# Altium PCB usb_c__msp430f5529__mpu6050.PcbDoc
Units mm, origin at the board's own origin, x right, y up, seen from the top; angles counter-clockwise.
Board outline 82 x 52 mm, 2 copper layers (Top, Bottom), stack 0 mm thick; 32 components, 26 nets, 203 pads, 80 vias.
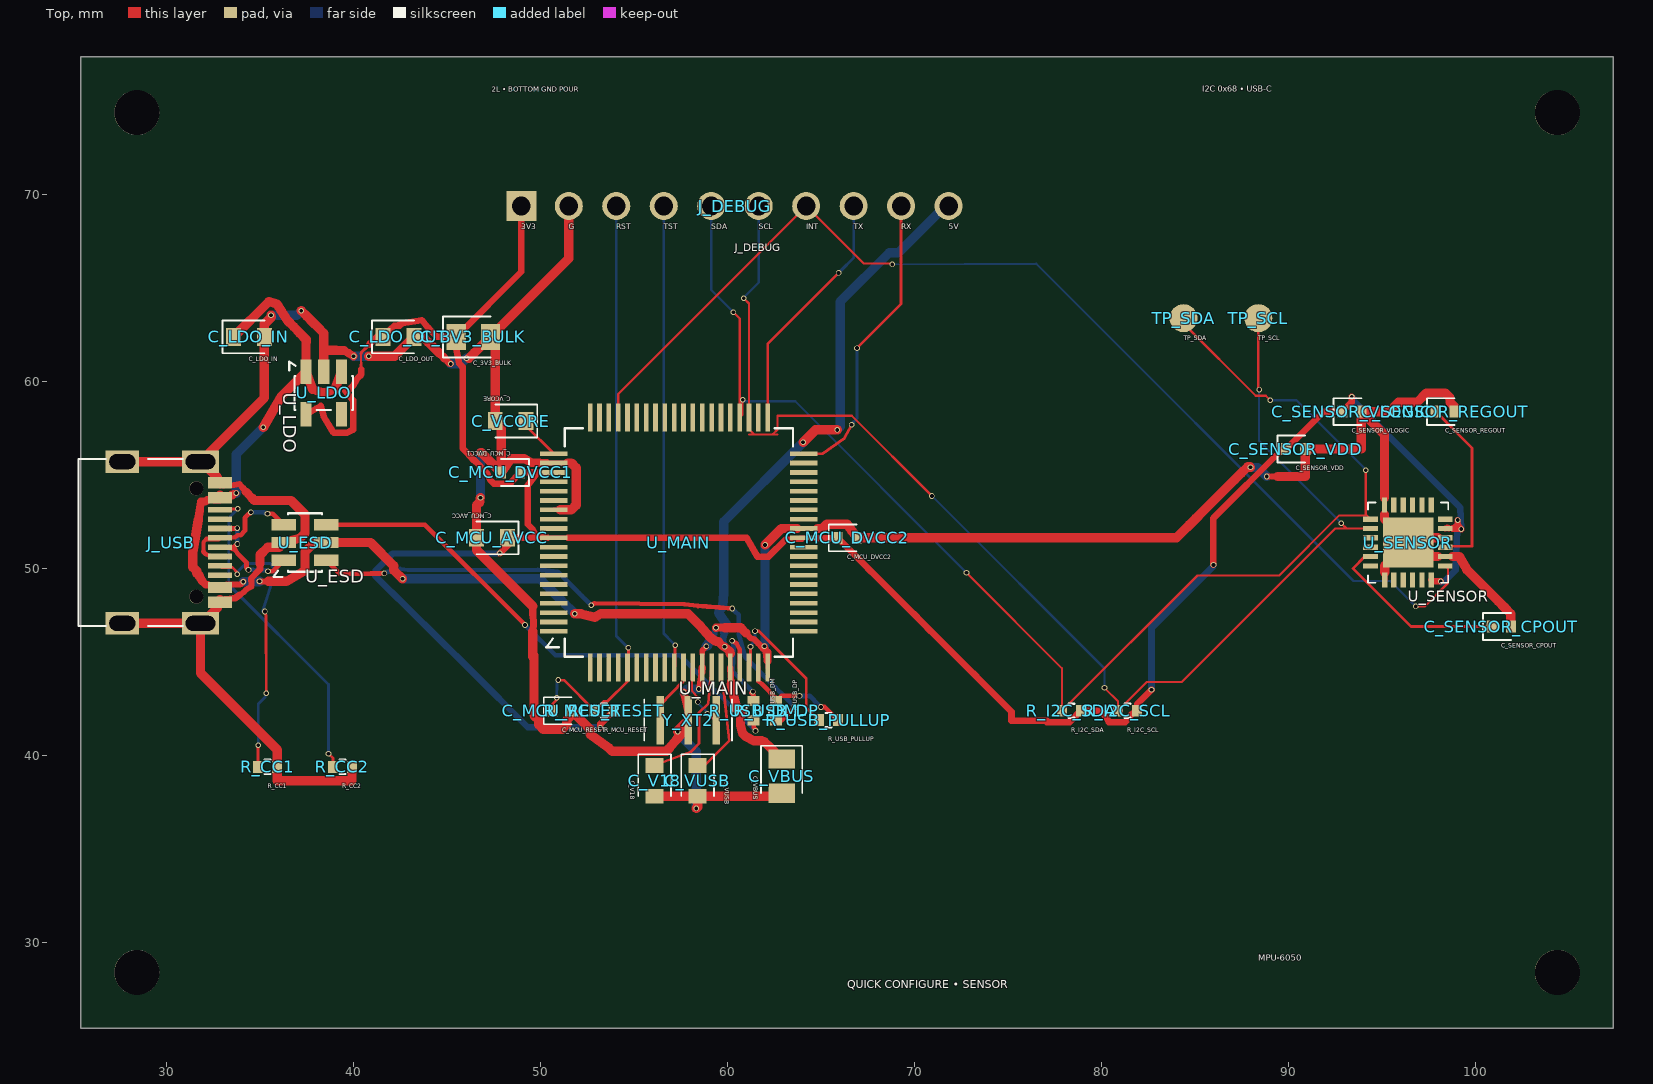
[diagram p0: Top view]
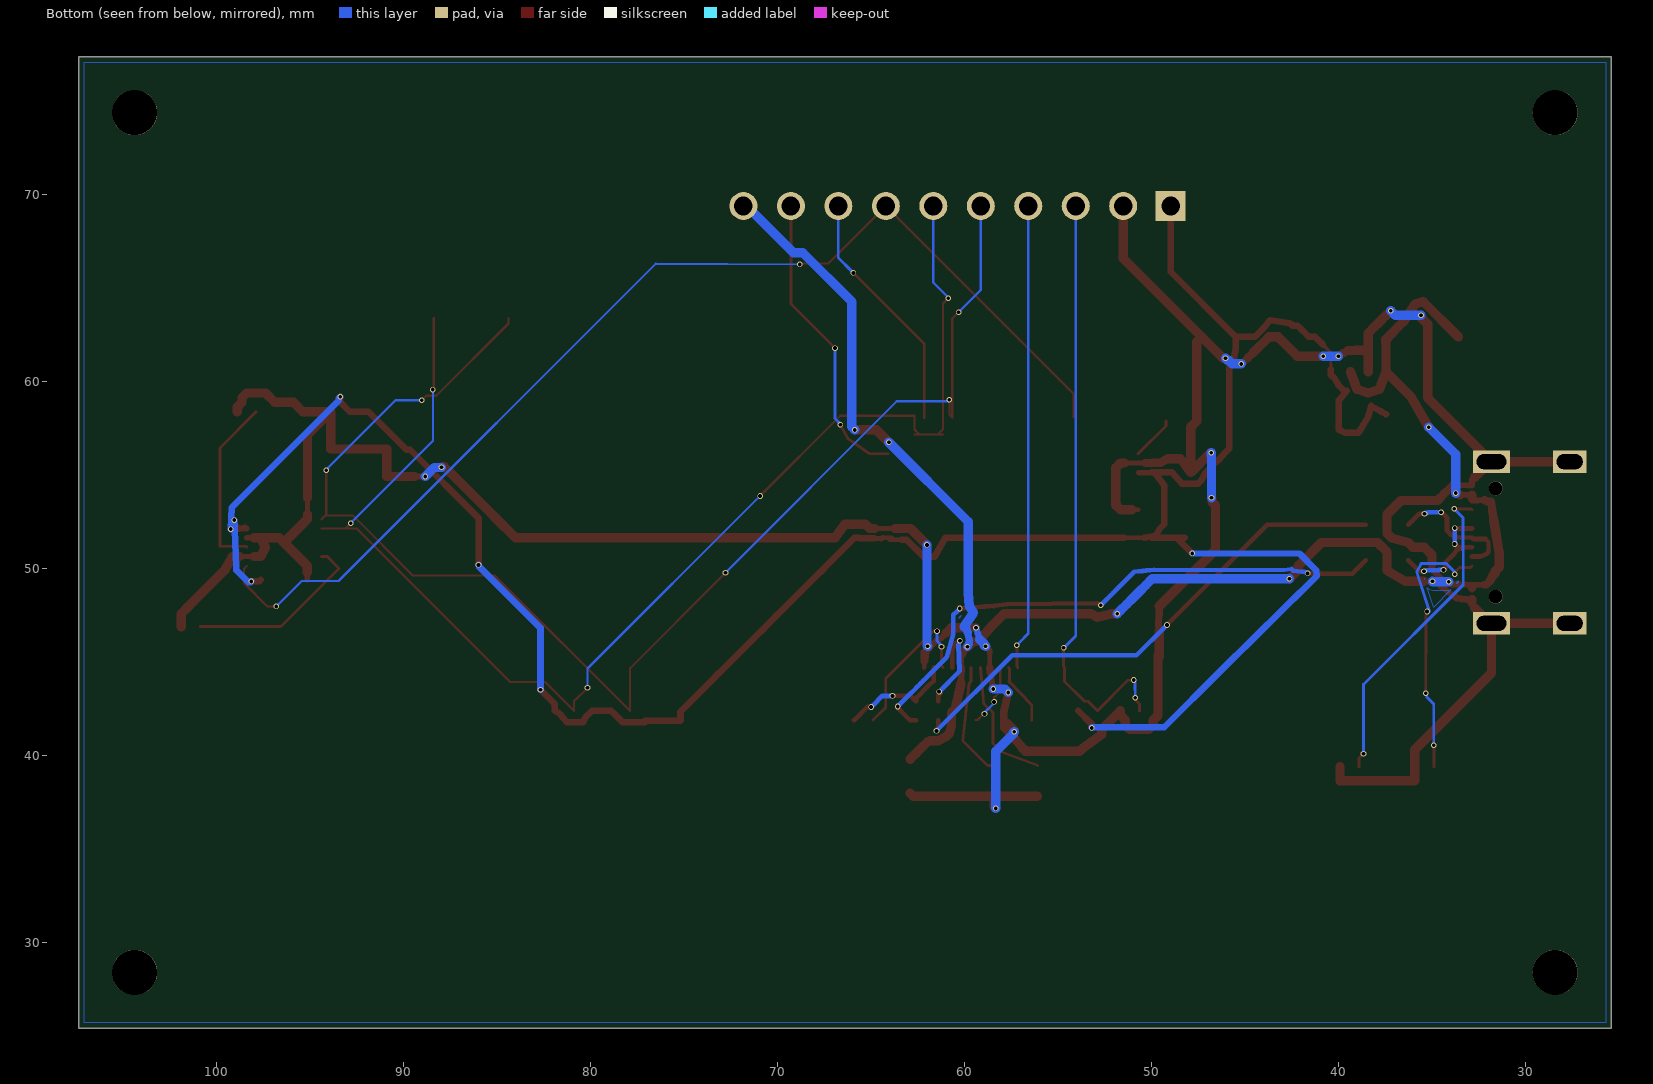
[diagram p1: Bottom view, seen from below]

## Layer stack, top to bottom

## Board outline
25.4,77.4 107.4,77.4 107.4,25.4 25.4,25.4

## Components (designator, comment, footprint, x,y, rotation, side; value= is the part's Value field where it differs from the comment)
C_3V3_BULK "" TSCIRCUIT-2.8500x1.4000mm 46.4,62.4 r0 top
C_LDO_IN "" TSCIRCUIT-2.4500x0.9500mm 34.4,62.4 r0 top
C_LDO_OUT "" TSCIRCUIT-2.4500x0.9500mm 42.4,62.4 r0 top
C_MCU_AVCC "" TSCIRCUIT-2.4500x0.9500mm 47.4,51.65 r180 top
C_MCU_DVCC1 "" TSCIRCUIT-1.5600x0.6400mm 48.4,55.15 r180 top
C_MCU_DVCC2 "" TSCIRCUIT-1.5600x0.6400mm 66.4,51.65 r0 top
C_MCU_RESET "" TSCIRCUIT-1.5600x0.6400mm 51.15,42.4 r0 top
C_SENSOR_CPOUT "" TSCIRCUIT-1.5600x0.6400mm 101.4,46.9 r0 top
C_SENSOR_REGOUT "" TSCIRCUIT-1.5600x0.6400mm 98.4,58.4 r0 top
C_SENSOR_VDD "" TSCIRCUIT-1.5600x0.6400mm 90.4,56.4 r0 top
C_SENSOR_VLOGIC "" TSCIRCUIT-1.5600x0.6400mm 93.4,58.4 r0 top
C_V18 "" TSCIRCUIT-0.9500x2.4500mm 56.1,38.65 r270 top
C_VBUS "" TSCIRCUIT-1.4000x2.8500mm 62.9,38.9 r270 top
C_VCORE "" TSCIRCUIT-2.4500x0.9500mm 48.4,57.9 r180 top
C_VUSB "" TSCIRCUIT-0.9500x2.4500mm 58.4,38.65 r270 top
J_DEBUG "" TSCIRCUIT-24.3600x1.5000mm 60.4,69.4 r0 top
J_USB "" TSCIRCUIT-6.7732x9.8502mm 30.113,51.4 r90 top
R_CC1 "" TSCIRCUIT-1.5600x0.6400mm 35.4,39.4 r0 top
R_CC2 "" TSCIRCUIT-1.5600x0.6400mm 39.4,39.4 r0 top
R_I2C_SCL "" TSCIRCUIT-1.5600x0.6400mm 81.4,42.4 r0 top
R_I2C_SDA "" TSCIRCUIT-1.5600x0.6400mm 78.4,42.4 r0 top
R_MCU_RESET "" TSCIRCUIT-1.5600x0.6400mm 53.4,42.4 r0 top
R_USB_DM "" TSCIRCUIT-0.6400x1.5600mm 61.4,42.4 r90 top
R_USB_DP "" TSCIRCUIT-0.6400x1.5600mm 62.6,42.4 r90 top
R_USB_PULLUP "" TSCIRCUIT-1.5600x0.6400mm 65.4,41.9 r0 top
TP_SCL "" TSCIRCUIT-1.5000x1.5000mm 88.4,63.4 r0 top
TP_SDA "" TSCIRCUIT-1.5000x1.5000mm 84.4,63.4 r0 top
U_ESD "" TSCIRCUIT-3.6000x2.5000mm 37.4,51.4 r0 top
U_LDO "" TSCIRCUIT-2.5000x3.6000mm 38.4,59.4 r270 top
U_MAIN "" TSCIRCUIT-14.8500x14.8500mm 57.4,51.4 r0 top
U_SENSOR "" TSCIRCUIT-4.8000x4.8000mm 96.4,51.4 r0 top
Y_XT2 "" TSCIRCUIT-3.4000x2.6000mm 57.9,41.9 r270 top

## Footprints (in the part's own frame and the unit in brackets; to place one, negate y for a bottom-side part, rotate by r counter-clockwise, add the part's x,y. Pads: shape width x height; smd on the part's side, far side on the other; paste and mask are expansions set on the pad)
TSCIRCUIT-0.6400x1.5600mm [mm]
  rect 0.54x0.64 smd: 1(-0.51,0) 2(0.51,0)
  silkscreen extent -0.15,-0.38 0.15,0.38
TSCIRCUIT-0.9500x2.4500mm [mm]
  rect 0.8x0.95 smd: 1(-0.825,0) 2(0.825,0)
  silkscreen extent -1.43,-0.87 0.82,0.87
TSCIRCUIT-1.4000x2.8500mm [mm]
  rect 1.025x1.4 smd: 1(-0.913,0) 2(0.913,0)
  silkscreen extent -1.62,-1.1 0.91,1.1
TSCIRCUIT-1.5000x1.5000mm [mm]
  round 1.5 smd: 1(0,0)
TSCIRCUIT-1.5600x0.6400mm [mm]
  rect 0.54x0.64 smd: 1(-0.51,0) 2(0.51,0)
  silkscreen extent -0.98,-0.72 0.51,0.72
TSCIRCUIT-2.4500x0.9500mm [mm]
  rect 0.8x0.95 smd: 1(-0.825,0) 2(0.825,0)
  silkscreen extent -1.43,-0.87 0.82,0.87
TSCIRCUIT-2.5000x3.6000mm [mm]
  rect 1.325x0.6 smd: 1(-1.137,-0.95) 2(-1.137,0) 3(-1.137,0.95) 4(1.138,0.95) 5(1.138,-0.95)
  silkscreen extent -1.69,-1.84 0.91,1.56
TSCIRCUIT-2.8500x1.4000mm [mm]
  rect 1.025x1.4 smd: 1(-0.913,0) 2(0.913,0)
  silkscreen extent -1.63,-1.1 0.91,1.1
TSCIRCUIT-3.4000x2.6000mm [mm]
  rect 2.6x0.4 smd: 1(0,1.5) 2(0,0) 3(0,-1.5)
  silkscreen extent -1.1,-2.35 1.1,2.35
TSCIRCUIT-3.6000x2.5000mm [mm]
  rect 1.325x0.6 smd: 1(-1.137,-0.95) 2(-1.137,0) 3(-1.137,0.95) 4(1.138,0.95) 5(1.138,0) 6(1.138,-0.95)
  silkscreen extent -1.69,-1.84 0.91,1.56
TSCIRCUIT-4.8000x4.8000mm [mm]
  rect 0.28x0.8 smd: 1(-1.25,2) 2(-0.75,2) 3(-0.25,2) 4(0.25,2) 5(0.75,2) 6(1.25,2) 13(1.25,-2) 14(0.75,-2) 15(0.25,-2) 16(-0.25,-2) 17(-0.75,-2) 18(-1.242,-2)
  rect 0.8x0.28 smd: 7(2,1.25) 8(2,0.75) 9(2,0.25) 10(2,-0.25) 11(2,-0.75) 12(2,-1.25) 19(-2,-1.25) 20(-2,-0.75) 21(-2,-0.25) 22(-2,0.25) 23(-2,0.75) 24(-2,1.25)
  rect 2.7x2.7 smd: 25(0.012,0)
  silkscreen extent -2.14,-2.15 2.16,2.15
TSCIRCUIT-6.7732x9.8502mm [mm]
  rect 0.3x1.3 smd: 1(-3.35,-2.737) 2(-3.05,-2.737) 3(-2.55,-2.737) 4(-2.25,-2.737) 5(-1.75,-2.737) 6(-1.25,-2.737) 7(-0.75,-2.737) 8(-0.25,-2.737) 9(0.25,-2.737) 10(0.75,-2.737) 11(1.25,-2.737) 12(1.75,-2.737) 13(2.55,-2.737) 14(2.25,-2.737) 15(3.35,-2.737) 16(3.05,-2.737)
  rect 1.2x2 hole 0.8 slot 1.6 at 90 deg: 17(-4.325,-1.693) 18(4.325,-1.693)
  rect 1.2x1.8 hole 0.8 slot 1.4 at 90 deg: 19(4.325,2.487) 20(-4.325,2.487)
  round 0.75 hole 0.75 unplated: NPTH-1(-2.9,-1.468) NPTH-2(2.9,-1.468)
  silkscreen extent -4.47,-0.75 4.47,4.83
TSCIRCUIT-14.8500x14.8500mm [mm]
  rect 1.475x0.25 smd: 1(-6.687,-4.75) 2(-6.687,-4.25) 3(-6.687,-3.75) 4(-6.687,-3.25) 5(-6.687,-2.75) 6(-6.687,-2.25) 7(-6.687,-1.75) 8(-6.687,-1.25) 9(-6.687,-0.75) 10(-6.687,-0.25) 11(-6.687,0.25) 12(-6.687,0.75) 13(-6.687,1.25) 14(-6.687,1.75) 15(-6.687,2.25) 16(-6.687,2.75) 17(-6.687,3.25) 18(-6.687,3.75) 19(-6.687,4.25) 20(-6.687,4.75) 41(6.687,4.75) 42(6.687,4.25) 43(6.687,3.75) 44(6.687,3.25) 45(6.687,2.75) 46(6.687,2.25) 47(6.687,1.75) 48(6.687,1.25) 49(6.687,0.75) 50(6.687,0.25) 51(6.687,-0.25) 52(6.687,-0.75) 53(6.687,-1.25) 54(6.687,-1.75) 55(6.687,-2.25) 56(6.687,-2.75) 57(6.687,-3.25) 58(6.687,-3.75) 59(6.687,-4.25) 60(6.687,-4.75)
  rect 0.25x1.475 smd: 21(-4.75,6.687) 22(-4.25,6.687) 23(-3.75,6.687) 24(-3.25,6.687) 25(-2.75,6.687) 26(-2.25,6.687) 27(-1.75,6.687) 28(-1.25,6.687) 29(-0.75,6.687) 30(-0.25,6.687) 31(0.25,6.687) 32(0.75,6.687) 33(1.25,6.687) 34(1.75,6.687) 35(2.25,6.687) 36(2.75,6.687) 37(3.25,6.687) 38(3.75,6.687) 39(4.25,6.687) 40(4.75,6.687) 61(4.75,-6.687) 62(4.25,-6.687) 63(3.75,-6.687) 64(3.25,-6.687) 65(2.75,-6.687) 66(2.25,-6.687) 67(1.75,-6.687) 68(1.25,-6.687) 69(0.75,-6.687) 70(0.25,-6.687) 71(-0.25,-6.687) 72(-0.75,-6.687) 73(-1.25,-6.687) 74(-1.75,-6.687) 75(-2.25,-6.687) 76(-2.75,-6.687) 77(-3.25,-6.687) 78(-3.75,-6.687) 79(-4.25,-6.687) 80(-4.75,-6.687)
  silkscreen extent -7.09,-6.11 6.11,6.11
TSCIRCUIT-24.3600x1.5000mm [mm]
  rect 1.6x1.6 hole 1: 1(-11.43,0)
  round 1.5 hole 1: 2(-8.89,0) 3(-6.35,0) 4(-3.81,0) 5(-1.27,0) 6(1.27,0) 7(3.81,0) 8(6.35,0) 9(8.89,0) 10(11.43,0)

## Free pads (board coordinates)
  round 2.4 hole 2.4 unplated: NPTH-3(28.4,28.4) NPTH-4(104.4,28.4) NPTH-5(28.4,74.4) NPTH-6(104.4,74.4)

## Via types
v1: diameter 0.3, hole 0.2, Top to Bottom, 80 vias

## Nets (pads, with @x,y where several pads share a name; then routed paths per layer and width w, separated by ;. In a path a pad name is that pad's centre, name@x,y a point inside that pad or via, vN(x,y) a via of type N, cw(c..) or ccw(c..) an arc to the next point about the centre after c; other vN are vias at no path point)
".J_DEBUG > .pin4 to .U_MAIN > .pin71": J_DEBUG.4 U_MAIN.71 | length 25
  Top w0.15: U_MAIN.71 57.2,44.762 v1(57.2,45.906)
  Bottom w0.15: J_DEBUG.4 56.59,46.53 57.036,46.085 57.036,46.07 v1(57.2,45.906)
".J_DEBUG > .pin8 to .U_MAIN > .pin40": J_DEBUG.8 U_MAIN.40 | length 13.2
  Top w0.15: U_MAIN.40 62.15,62.028 v1(65.944,65.822)
  Bottom w0.15: v1(65.944,65.822) 66.057,65.935 66.057,65.937 66.75,66.63 J_DEBUG.8
".J_DEBUG > .pin9 to .U_MAIN > .pin41": J_DEBUG.9 U_MAIN.41 | length 16
  Top w0.15: U_MAIN.41 65.085,56.148 66.253,56.984 v1(66.641,57.7) ; v1(66.928,61.802) 67.007,61.881 69.29,64.164 J_DEBUG.9
  Bottom w0.15: v1(66.641,57.7) 66.647,57.714 66.647,57.753 66.928,58.034 v1(66.928,61.802)
GND: C_3V3_BULK.2 C_LDO_IN.2 C_LDO_OUT.2 C_MCU_AVCC.2 C_MCU_DVCC1.2 C_MCU_DVCC2.2 C_MCU_RESET.2 C_SENSOR_CPOUT.2 C_SENSOR_REGOUT.2 C_SENSOR_VDD.2 C_SENSOR_VLOGIC.2 C_V18.2 C_VBUS.2 C_VCORE.2 C_VUSB.2 J_DEBUG.2 J_USB.1 J_USB.2 J_USB.15 J_USB.16 J_USB.17 J_USB.18 J_USB.19 J_USB.20 R_CC1.2 R_CC2.2 U_ESD.2 U_LDO.2 U_MAIN.14 U_MAIN.19 U_MAIN.49 U_MAIN.61 U_MAIN.68 U_SENSOR.1 U_SENSOR.9 U_SENSOR.11 U_SENSOR.18 U_SENSOR.25 Y_XT2.2 | length 213.3
  Top w0.25: U_MAIN.14 U_MAIN.14@51.046,53.15 ; U_MAIN.19 U_MAIN.19@51.45,55.65 ; U_MAIN.68 58.65,45.166 U_MAIN.68@58.65,45.45 ; U_MAIN.61@62.119,45.056 U_MAIN.61 U_MAIN.61@62.15,45.052 ; U_MAIN.49@63.716,52.15 U_MAIN.49 64.552,52.15 U_MAIN.49@64.825,52.15
  Top w0.27: U_MAIN.19@50.327,55.655 U_MAIN.19
  Top w0.28: 95.15,52.9 95.15,53 95.15,53.025 95.15,53.15 95.15,53.275 U_SENSOR.1 95.15,53.525 95.15,53.65 95.15,53.775 95.15,53.8 ; U_SENSOR.18 95.158,49.525 95.158,49.65 95.158,49.775 95.158,49.8 ; U_SENSOR.11@98,50.65 U_SENSOR.11 98.8,50.65 ; U_SENSOR.9@98,51.65 U_SENSOR.9 98.025,51.65 U_SENSOR.9@98,51.65
  Top w0.3: J_USB.1@32.699,47.9 J_USB.1 J_USB.2@32.849,48.2 ; 32.699,54.9 J_USB.15 J_USB.16@32.849,54.6 ; J_USB.2 32.945,48.339 33.037,48.35 J_USB.2@33.13,48.35 ; J_USB.16 J_USB.16@32.945,54.461 ; 58.65,45.45 58.65,45.62 v1(58.873,45.843)
  Top w0.31: J_USB.16 J_USB.15@32.849,54.6 ; v1(46.035,61.257) v1@46.17,61.257
  Top w0.312: J_USB.16@32.945,54.461 33.037,54.45 33.314,54.465 33.592,54.479 33.9,54.525 ; 33.9,48.587 34.134,48.744 34.254,48.877 34.525,49.056
  Top w0.325: 34.525,49.056 34.521,49.482 34.758,49.727 ; v1(58.466,43.56) 58.527,43.886 58.588,44.212 U_MAIN.68@58.619,44.462 ; 60.99,46.552 61.28,46.262 61.4,46.244 61.634,46.009 v1@61.869,45.775 ; v1(88.853,54.932) 89.148,54.932 89.443,54.933
  Top w0.331: 33.9,54.525 34.068,54.322
  Top w0.35: 34.068,54.322 34.235,54.12 ; 34.758,49.727 34.994,49.971 ; v1@45.136,60.978 45.176,60.978 v1(45.198,60.956)
  Top w0.375: J_USB.2@33.13,48.35 33.398,48.391 33.666,48.431 33.9,48.587 ; 34.99,50.279 34.994,49.971 ; 44.851,61.262 v1@45.136,60.978 ; 49.589,46.639 49.619,47.088 49.589,47.535 ; v1@61.869,45.775 62.15,45.525 ; v1(61.976,45.843) U_MAIN.61@62.088,45.4
  Top w0.383: U_MAIN.61@62.088,45.4 U_MAIN.61@62.119,45.056
  Top w0.4: 49.589,47.535 49.59,47.983 ; 57.585,41.171 57.9,41.486 Y_XT2.2 ; v1(57.659,43.378) 57.9,42.346 Y_XT2.2 ; Y_XT2.2@57.7,41.7 Y_XT2.2 ; U_MAIN.68@58.619,44.462 U_MAIN.68 ; U_MAIN.61@62.15,45.052 62.15,45.525
  Top w0.425: v1(59.384,46.838) 59.388,46.842 59.451,46.842 59.867,46.842
  Top w0.437: 39.494,61.681 39.745,61.524 v1(39.996,61.367)
  Top w0.45: 34.235,54.12 34.58,53.765 ; 44.567,61.547 44.851,61.262 ; 49.556,55.666 49.942,55.66 U_MAIN.19@50.327,55.655
  Top w0.475: v1(35.576,63.564) v1@35.602,63.464 ; 39.056,61.681 39.494,61.681 ; 49.119,55.884 49.556,55.666 ; 60.701,46.842 60.99,46.552 ; v1@87.946,55.458 v1(87.983,55.421)
  Top w0.5: J_USB.20 J_USB.17 ; J_USB.19 J_USB.18 ; J_USB.1@32.699,47.9 32.474,47.675 31.874,47.075 J_USB.17 ; 32.699,54.9 32.474,55.125 31.874,55.725 J_USB.18 ; J_USB.1@32.849,48.2 J_USB.2 ; 34.58,53.765 34.695,53.65 35.65,53.65 36.65,53.65 37.4,52.9 37.4,51.9 37.15,51.65 U_ESD.2 36.013,51.15 35.4,51.15 34.987,50.737 34.987,50.586 34.99,50.279 ; v1@35.602,63.464 35.414,63.275 35.225,63.086 35.225,62.743 C_LDO_IN.2 35.225,59.144 J_USB.18 ; v1(37.2,63.8) 37.5,63.5 37.8,63.2 38.1,62.9 38.4,62.6 38.4,62.188 38.4,61.775 38.4,61.363 38.4,60.95 U_LDO.2 38.4,61.681 39.056,61.681 ; R_CC2.2 39.91,38.65 35.91,38.65 R_CC1.2 35.908,39.86 35.906,40.32 31.806,44.42 J_USB.17 ; v1(40.804,61.361) 40.809,61.366 40.903,61.366 41.333,61.366 41.762,61.366 42.191,61.366 42.536,61.711 42.88,62.055 C_LDO_OUT.2 43.713,62.4 43.998,62.116 44.282,61.831 44.567,61.547 ; v1@46.17,61.257 46.456,61.543 C_3V3_BULK.2 ; v1(46.787,53.8) 46.759,53.772 46.759,53.574 46.575,53.389 C_MCU_AVCC.2 46.575,50.998 49.59,47.983 ; v1(46.8,56.2) 46.84,56.2 C_MCU_DVCC1.2 ; 49.119,55.884 48.791,55.884 48.462,55.884 48.176,55.598 48.176,55.517 C_MCU_DVCC1.2 ; 49.589,46.639 49.589,46.191 49.589,45.743 49.588,45.295 49.65,45.357 49.65,42.15 49.9,41.9 49.9,41.65 50.15,41.4 51.15,41.4 51.4,41.65 51.4,41.9 51.66,42.16 C_MCU_RESET.2 52.65,41.41 52.65,41.15 53.639,40.421 53.827,40.233 56.733,40.233 56.9,40.4 57.27,40.856 57.585,41.171 ; U_MAIN.14@51.046,53.15 51.65,53.15 51.9,53.4 51.9,55.4 51.65,55.65 51.45,55.65 ; J_DEBUG.2 51.51,66.597 C_3V3_BULK.2 ; C_V18.2 C_VUSB.2 ; v1(57.342,41.276) 57.342,41.342 57.7,41.7 ; v1(58.327,37.175) 58.4,37.248 C_VUSB.2 ; 59.867,46.842 60.284,46.842 60.701,46.842 ; v1(62.011,51.27) 62.891,52.15 63.344,52.15 U_MAIN.49@63.716,52.15 ; C_VBUS.2 62.737,37.825 C_VUSB.2 ; 64.825,52.15 65.016,52.15 65.072,52.15 65.306,52.384 65.671,52.384 66.035,52.384 66.4,52.384 66.655,52.017 C_MCU_DVCC2.2 67.399,51.65 67.888,51.65 68.377,51.65 68.865,51.65 69.354,51.65 69.843,51.65 70.332,51.65 70.821,51.65 71.31,51.65 71.799,51.65 72.287,51.65 72.776,51.65 73.265,51.65 73.754,51.65 74.243,51.65 74.732,51.65 75.221,51.65 75.709,51.65 76.198,51.65 76.687,51.65 77.176,51.65 77.665,51.65 78.154,51.65 78.643,51.65 79.131,51.65 79.62,51.65 80.109,51.65 80.598,51.65 81.087,51.65 81.576,51.65 82.065,51.65 82.553,51.65 83.042,51.65 83.531,51.65 84.02,51.65 84.366,51.996 84.712,52.342 85.059,52.689 85.405,53.035 85.751,53.381 86.097,53.727 86.443,54.073 86.79,54.42 87.136,54.766 87.482,55.112 87.828,55.458 v1@87.946,55.458 ; 89.443,54.933 90.91,54.933 C_SENSOR_VDD.2 93.91,56.4 C_SENSOR_VLOGIC.2 ; 95.15,52.9 95.15,52.775 95.15,52.662 95.159,52.654 95.247,52.565 95.336,52.477 U_SENSOR.25 ; 95.15,53.8 95.15,53.9 95.15,54.025 95.15,54.15 95.15,54.275 95.15,54.4 95.15,57.16 C_SENSOR_VLOGIC.2 ; 95.158,49.8 95.158,49.9 95.158,50.025 95.158,50.145 95.161,50.149 95.25,50.237 95.338,50.325 U_SENSOR.25 ; U_SENSOR.11@98,50.65 97.762,50.65 97.65,50.65 97.4,51.15 U_SENSOR.25@97.65,51.65 ; 98.8,50.65 99.15,50.65 99.558,49.946 99.894,49.61 100.23,49.274 100.566,48.938 100.902,48.602 101.238,48.266 101.574,47.93 101.91,47.594 101.91,47.247 C_SENSOR_CPOUT.2 ; C_SENSOR_REGOUT.2 98.9,58.4 98.9,58.65 98.65,58.9 98.65,59.15 98.4,59.4 97.4,59.4 96.9,58.9 95.9,58.9 95.4,58.4 C_SENSOR_VLOGIC.2 ; C_3V3_BULK.2 47.575,62.138 C_VCORE.2 47.89,57.585 C_MCU_DVCC1.2 ; U_SENSOR.25 96.662,51.65 97.4,51.65 97.525,51.65 U_SENSOR.25@97.65,51.65 ; U_SENSOR.25@97.65,51.65 97.762,51.65 98,51.65 97.9,51.65 97.775,51.65 U_SENSOR.25@97.65,51.65
  Bottom w0.35: 59.182,46.209 59.283,46.523 v1(59.384,46.838)
  Bottom w0.475: v1(87.983,55.421) 88.36,55.421 88.579,55.202
  Bottom w0.5: v1(35.576,63.564) 36.964,63.564 v1(37.2,63.8) ; v1(39.996,61.367) 39.999,61.364 40.057,61.364 40.06,61.361 40.432,61.361 v1(40.804,61.361) ; v1(45.198,60.956) 45.673,60.956 45.867,61.15 45.928,61.15 v1(46.035,61.257) ; v1(46.787,53.8) 46.787,56.032 46.799,56.044 v1(46.8,56.2) ; v1(57.342,41.276) 57.393,41.226 57.393,41.159 58.327,40.225 v1(58.327,37.175) ; v1(57.659,43.378) 57.841,43.56 v1(58.466,43.56) ; v1(58.873,45.843) 58.98,45.95 58.98,46.007 59.182,46.209 ; v1(61.976,45.843) 62.011,45.878 v1(62.011,51.27) ; 88.579,55.202 88.799,54.982 88.803,54.982 v1(88.853,54.932)
MAIN_RESET: C_MCU_RESET.1 J_DEBUG.3 R_MCU_RESET.1 U_MAIN.76 | length 32.6
  Top w0.15: C_MCU_RESET.1 50.64,42.762 50.914,43.036 50.914,43.088 v1(50.862,43.096) ; v1(50.946,44.044) 51.279,44.011 R_MCU_RESET.1 53.394,42.904 53.584,42.904 54.65,43.971 U_MAIN.76 54.7,44.762 v1(54.7,45.763)
  Bottom w0.15: v1(50.862,43.096) 50.884,43.837 50.863,43.858 50.863,43.961 v1(50.946,44.044) ; J_DEBUG.3 54.05,46.405 54.584,45.871 54.584,45.864 v1(54.7,45.763)
MSP_USB_PUR: R_USB_PULLUP.1 U_MAIN.63 | length 8.4
  Top w0.15: U_MAIN.63 61.232,44.794 v1(61.232,45.826) ; v1(61.474,46.66) 61.49,46.676 61.546,46.676 61.659,46.676 64.215,44.12 64.215,42.575 R_USB_PULLUP.1
  Bottom w0.15: v1(61.232,45.826) 61.311,45.905 61.311,45.979 61.474,46.142 v1(61.474,46.66)
MSP_V18: C_V18.1 U_MAIN.67 | length 7
  Top w0.15: C_V18.1 58.047,40.206 58.483,40.641 58.483,42.244 58.483,42.298 58.975,42.79 U_MAIN.67
MSP_VCORE: C_VCORE.1 U_MAIN.20 | length 2.4
  Top w0.15: C_VCORE.1 49.225,57.638 U_MAIN.20
MSP_VUSB: C_VUSB.1 U_MAIN.66 | length 6.2
  Top w0.15: C_VUSB.1 58.776,39.475 60.099,40.798 59.768,43.814 59.659,43.966 59.659,44.703 U_MAIN.66
SENSOR_CPOUT: C_SENSOR_CPOUT.1 U_SENSOR.20 | length 9.9
  Top w0.15: U_SENSOR.20 94.095,50.65 93.459,50.014 96.573,46.9 C_SENSOR_CPOUT.1
SENSOR_INT: J_DEBUG.7 U_MAIN.24 U_SENSOR.12 | length 60.2
  Top w0.12: U_MAIN.24 54.15,59.34 J_DEBUG.7 67.284,66.326 68.686,66.326 68.763,66.326 v1(68.811,66.278) ; v1(96.822,47.98) 97.299,47.98 98.551,49.232 98.551,49.999 U_SENSOR.12
  Bottom w0.12: v1(68.811,66.278) 76.513,66.314 93.491,49.336 95.458,49.336 96.818,47.976 v1(96.822,47.98)
SENSOR_REGOUT: C_SENSOR_REGOUT.1 U_SENSOR.10 | length 9.5
  Top w0.15: C_SENSOR_REGOUT.1 99.832,56.458 99.832,51.203 98.453,51.203 U_SENSOR.10
SENSOR_SCL: J_DEBUG.6 R_I2C_SCL.1 TP_SCL.1 U_MAIN.38 U_SENSOR.23 | length 73.6
  Top w0.12: v1(60.87,64.47) 61.15,64.19 U_MAIN.38 61.15,57.457 61.417,57.19 61.15,57.175 62.677,57.175 62.416,57.19 62.677,57.451 62.677,58.178 66.648,58.178 v1(70.935,53.89) ; v1(80.172,43.627) 80.19,43.609 80.89,42.909 R_I2C_SCL.1 82.431,43.941 84.301,43.941 92.51,52.15 U_SENSOR.23 93.115,52.15 v1(92.839,52.426) ; TP_SCL.1 88.4,59.667 88.388,59.655 88.388,59.636 v1(88.442,59.582)
  Bottom w0.12: v1@60.852,64.488 v1(60.87,64.47) ; v1@60.852,64.489 61.67,65.307 J_DEBUG.6 ; v1(70.935,53.89) 71.002,53.824 80.172,44.654 v1(80.172,43.627) ; v1(88.442,59.582) 88.442,56.826 92.791,52.477 92.791,52.474 v1(92.839,52.426)
SENSOR_SDA: J_DEBUG.5 R_I2C_SDA.1 TP_SDA.1 U_MAIN.37 U_SENSOR.24 | length 75.3
  Top w0.12: v1(60.316,63.724) 60.65,63.39 U_MAIN.37 60.81,58.247 v1(60.81,59.037) ; v1(72.788,49.782) 72.961,49.609 77.89,44.679 R_I2C_SDA.1 77.9,42.4 85.141,49.64 89.523,49.64 92.735,52.852 94.198,52.852 U_SENSOR.24 94.153,52.897 v1(94.153,55.269) ; TP_SDA.1 84.4,63.116 88.265,59.251 88.798,59.251 88.951,59.098 v1(89.033,59.016)
  Bottom w0.12: J_DEBUG.5 59.13,64.91 60.198,63.842 ; 60.198,63.842 v1(60.316,63.724) ; v1(60.81,59.037) 60.839,59.008 60.839,58.951 63.619,58.951 v1(72.788,49.782) ; v1(89.033,59.016) 90.441,59.016 94.041,55.416 94.041,55.381 v1(94.153,55.269)
usb-dm-mcu: R_USB_DM.2 U_MAIN.64 | length 5.4
  Top w0.25: v1(60.246,46.145) 60.489,45.997 60.65,45.687 U_MAIN.64 ; v1(61.362,43.423) 61.284,43.345 61.4,43.229 R_USB_DM.2
  Bottom w0.25: v1(60.246,46.145) 60.268,46.068 60.322,45.933 60.269,44.516 v1(61.362,43.423)
usb-dm-phy: R_USB_DM.1 U_ESD.4 | length 28.1
  Top w0.25: U_ESD.4 38.787,52.35 43.816,52.35 v1(49.169,46.986) ; R_USB_DM.1 61.4,41.506 61.482,41.424 61.482,41.339 v1(61.5,41.321)
  Bottom w0.25: v1(49.169,46.986) 49.299,46.867 ; 49.3,46.867 50.785,45.381 50.933,45.375 57.44,45.372 v1(61.5,41.321)
usb-dm-port: J_USB.7 J_USB.9 U_ESD.3 | length 7.1
  Top w0.238: 31.968,50.937 31.968,51.181 31.968,51.425 32.129,51.586
  Top w0.25: 31.968,50.937 31.962,50.9 32.087,50.775 32.453,50.65 32.651,50.65 J_USB.7 ; 32.129,51.586 32.348,51.586 32.566,51.586 32.785,51.586 J_USB.9 33.626,51.678 33.788,51.78 33.961,51.799 34.186,52.025 34.186,52.733 34.392,52.938 34.433,52.938 v1(34.503,53.014) ; v1(35.389,52.933) 35.68,52.933 U_ESD.3
  Bottom w0.25: v1(34.503,53.014) 35.203,53.014 35.241,52.976 35.346,52.976 v1(35.389,52.933)
usb-dp-mcu: R_USB_DP.2 R_USB_PULLUP.2 U_MAIN.62 | length 6.2
  Top w0.25: U_MAIN.62 61.65,44.475 61.65,44.238 61.65,44.002 61.65,43.975 61.824,43.846 61.934,43.736 62.044,43.626 62.18,43.486 62.32,43.346 62.46,43.206 62.6,43.066 R_USB_DP.2 62.89,43.2 63.73,43.2 63.845,43.2 v1(63.853,43.192) ; v1(65,42.6) 65.21,42.6 R_USB_PULLUP.2
  Bottom w0.25: v1(63.853,43.192) 64.393,43.192 64.894,42.691 64.909,42.691 v1(65,42.6)
usb-dp-phy: R_USB_DP.1 U_ESD.6 | length 30.8
  Top w0.25: U_ESD.6 38.684,50.304 38.83,50.158 38.976,50.012 39.122,49.866 39.268,49.72 39.506,49.723 39.744,49.725 39.981,49.728 40.219,49.731 40.457,49.733 40.695,49.736 40.933,49.739 41.171,49.742 41.408,49.744 v1(41.646,49.747) ; v1(52.706,48.046) 52.9,48.15 57.7,48.1 58.426,48.008 58.655,47.991 58.884,47.973 59.113,47.956 59.342,47.939 59.571,47.922 59.799,47.904 60.028,47.887 v1(60.257,47.87) ; R_USB_DP.1 62.757,41.89 62.915,41.89 63.09,42.065 63.265,42.24 63.439,42.415 63.614,42.59 v1(63.577,42.627)
  Bottom w0.225: 42.502,49.978 42.705,49.95 42.908,49.922 43.147,49.922 43.386,49.922 43.625,49.922 43.864,49.922 44.103,49.923 44.342,49.923 44.58,49.923 44.819,49.923 45.058,49.923 45.297,49.923 45.536,49.923 45.775,49.922 46.014,49.922 46.253,49.922 46.491,49.922 46.73,49.922 46.969,49.922 47.208,49.922 47.447,49.922 47.686,49.922 47.925,49.922 48.164,49.922 48.402,49.922 48.641,49.922 48.88,49.922 49.119,49.922 49.358,49.922 49.597,49.922 49.836,49.922 49.85,49.95
  Bottom w0.25: v1(41.646,49.747) 41.662,49.777 41.733,49.777 41.797,49.841 41.953,49.841 42.192,49.868 42.431,49.895 42.502,49.978 ; 49.85,49.95 50.06,49.925 50.27,49.899 50.481,49.874 50.696,49.858 50.911,49.841 51.074,49.678 51.237,49.515 51.4,49.352 51.564,49.188 51.727,49.025 51.89,48.862 52.053,48.699 52.216,48.536 52.38,48.372 52.543,48.209 v1(52.706,48.046) ; v1(60.257,47.87) 60.425,47.702 60.594,47.533 60.598,47.39 60.599,47.168 60.6,46.945 60.601,46.723 60.602,46.5 60.956,45.259 61.13,45.084 61.305,44.908 61.48,44.733 61.655,44.557 61.829,44.382 62.004,44.206 62.179,44.031 62.354,43.855 62.528,43.68 62.703,43.504 62.878,43.329 63.053,43.153 63.227,42.978 63.402,42.802 v1(63.577,42.627)
usb-dp-port: J_USB.8 J_USB.10 U_ESD.1 | length 7.2
  Top w0.25: J_USB.10 33.599,52.15 v1(33.767,52.17) ; v1(33.78,51.32) 33.57,51.15 J_USB.8 33.052,51.15 33.256,51.15 33.65,51.025 33.781,50.828 33.943,50.666 34.104,50.505 34.265,50.344 34.265,50.195 34.265,50.046 34.387,49.924 v1(34.375,49.936) ; v1(35.42,49.857) 35.67,49.857 35.818,50.005 35.966,50.153 36.114,50.302 U_ESD.1
  Bottom w0.25: v1(33.767,52.17) 33.768,51.418 33.757,51.407 33.757,51.359 v1(33.78,51.32) ; v1(34.375,49.936) 34.614,49.93 34.853,49.924 35.092,49.919 35.331,49.913 35.377,49.867 35.41,49.867 v1(35.42,49.857)
USB_CC1: J_USB.6 R_CC1.1 | length 14.8
  Top w0.15: J_USB.6 32.934,50.065 33.51,50.065 33.793,49.782 v1(33.776,49.708) ; R_CC1.1 34.89,40.4 34.89,40.545 v1(34.901,40.556) ; v1(35.254,47.711) 35.279,47.686 35.279,47.547 35.308,47.518 v1(35.325,43.329)
  Bottom w0.15: v1(33.776,49.708) 33.735,49.629 33.775,49.825 34.225,50.275 35.575,50.275 35.8,49.825 35.125,47.714 v1(35.254,47.711) ; v1(34.901,40.556) 34.901,42.777 35.274,43.15 35.274,43.278 v1(35.325,43.329)
USB_CC2: J_USB.12 R_CC2.1 | length 17.3
  Top w0.15: J_USB.12 32.899,53.2 v1(33.8,53.2) ; v1(38.657,40.105) 38.688,40.074 38.688,40.066 38.89,39.864 R_CC2.1
  Bottom w0.15: v1(33.8,53.2) 33.797,53.197 33.325,52.725 33.32,49.14 38.656,43.812 v1(38.657,40.105)
VBUS5: C_LDO_IN.1 C_VBUS.1 J_DEBUG.10 J_USB.3 J_USB.4 J_USB.13 J_USB.14 U_ESD.5 U_LDO.1 U_LDO.3 U_MAIN.65 | length 96.4
  Top w0.25: U_MAIN.65@60.132,45.45 60.14,45.14 60.14,44.723 U_MAIN.65 60.15,44.806 60.15,44.9 60.15,44.993 60.15,45.087 60.15,45.181 60.15,45.274 60.15,45.368 U_MAIN.65@60.15,45.45
  Top w0.275: J_USB.3 J_USB.4@32.849,49
  Top w0.3: 32.181,53.666 32.536,53.65 J_USB.14 32.849,53.8 ; J_USB.4@32.199,49.15 J_USB.4 ; J_USB.3@32.849,49 J_USB.4 ; J_USB.13 32.943,53.95 33.037,53.95 33.13,53.95 33.224,53.95 33.318,53.95 33.412,53.95 33.499,53.95 ; J_USB.4@33.21,49.15 J_USB.4
  Top w0.325: J_USB.4@33.21,49.15 33.57,49.15 33.931,49.15 v1(34.096,49.305) ; v1(34.961,49.323) 35.441,49.323
  Top w0.33: U_MAIN.65 60.175,44.256 U_MAIN.65@60.19,43.975
  Top w0.337: v1@33.571,54.018 33.627,54.018 v1(33.716,54.044)
  Top w0.375: 33.504,53.95 33.505,53.951 v1@33.571,54.018
  Top w0.4: 31.9,49.338 32.087,49.15 J_USB.4@32.199,49.15
  Top w0.437: 31.76,53.102 31.838,53.588 32.056,53.588 32.181,53.666
  Top w0.45: 31.682,52.616 31.76,53.102 ; 59.5,46.1 59.7,45.9 59.983,45.713 60.129,45.567 60.132,45.45 ; v1(59.846,45.82) 60.15,45.584 60.15,45.462 ; U_MAIN.65@60.19,43.975 60.2,43.8
  Top w0.475: 31.752,49.605 31.9,49.338 ; J_USB.13@32.849,53.8 J_USB.13 ; 33.499,53.95 33.504,53.95
  Top w0.5: 31.682,52.616 31.605,52.13 31.4,50.9 31.4,50.078 31.605,49.873 31.605,49.753 31.752,49.605 ; C_LDO_IN.1 35.461,64.286 35.9,64.15 36.458,63.273 36.791,62.936 37.123,62.598 37.456,62.261 37.454,61.83 37.453,61.399 37.451,60.968 U_LDO.1 ; v1(35.161,57.566) 36.142,59.229 U_LDO.1 ; 35.441,49.323 35.921,49.323 36.401,49.323 37.4,49.9 37.4,50.9 37.9,51.4 U_ESD.5 40.9,51.4 42.15,50.15 42.15,49.922 v1(42.617,49.455) ; U_LDO.3 39,59.6 38.4,59.4 37.8,59.6 U_LDO.1 ; v1(51.827,47.592) 52.164,47.585 52.9,47.4 53.226,47.592 53.692,47.592 54.158,47.592 54.624,47.592 55.09,47.592 55.557,47.592 56.023,47.592 56.489,47.592 56.955,47.592 57.422,47.592 57.888,47.592 58.198,47.282 58.508,46.972 59.1,46.3 59.4,46.1 59.5,46.1 ; 60.15,45.45 60.15,45.462 ; 60.2,43.8 60.3,43.367 60.4,42.933 60.5,42.5 60.7,42.3 60.7,41.633 60.8,41.2 61,41 61.4,40.8 61.8,40.8 61.972,40.74 62.281,40.431 62.591,40.122 C_VBUS.1 ; v1(64.045,56.757) 64.713,57.425 v1(65.876,57.425)
  Bottom w0.387: 59.776,45.958 59.776,46.048 59.728,46.15 59.838,46.587
  Bottom w0.45: 59.776,45.958 v1(59.846,45.82) ; 59.838,46.587 59.947,47.025
  Bottom w0.5: v1(33.716,54.044) 33.716,56.121 v1(35.161,57.566) ; v1(34.096,49.305) 34.943,49.305 v1(34.961,49.323) ; v1(42.617,49.455) 43.107,49.455 43.597,49.455 44.086,49.455 44.576,49.455 45.066,49.455 45.556,49.455 46.046,49.455 46.535,49.455 47.025,49.455 47.515,49.455 48.005,49.455 48.495,49.455 48.984,49.455 49.474,49.455 49.964,49.455 50.304,49.115 50.643,48.776 50.983,48.436 51.323,48.096 51.662,47.757 v1(51.827,47.592) ; 59.947,47.025 59.947,46.978 60.025,46.9 59.525,47.65 59.753,48.015 59.779,48.348 59.804,48.681 59.804,52.516 v1(64.045,56.757) ; v1(65.876,57.425) 66.038,57.587 66.038,58.195 66.038,64.288 68.65,66.9 69.15,66.9 71.65,69.4 J_DEBUG.10
VCC_3V3: C_3V3_BULK.1 C_LDO_OUT.1 C_MCU_AVCC.1 C_MCU_DVCC1.1 C_MCU_DVCC2.1 C_SENSOR_VDD.1 C_SENSOR_VLOGIC.1 J_DEBUG.1 R_I2C_SCL.2 R_I2C_SDA.2 R_MCU_RESET.2 U_LDO.5 U_MAIN.11 U_MAIN.18 U_MAIN.50 U_SENSOR.8 U_SENSOR.13 | length 146
  Top w0.12: 40.39,61.48 40.397,61.207 40.403,60.935
  Top w0.15: 40.39,61.48 40.416,61.576 40.622,61.782
  Top w0.162: 40.403,60.935 40.41,60.662
  Top w0.2: 40.622,61.782 40.829,61.988
  Top w0.25: 49.775,55.075 49.978,55.115 50.212,55.115 50.445,55.115 50.678,55.115 U_MAIN.18 50.619,55.15 50.525,55.15 50.432,55.15 50.338,55.15 50.244,55.15 50.15,55.15 50.057,55.15 U_MAIN.18@49.976,55.15 ; U_MAIN.11@49.975,51.65 50.056,51.65 50.15,51.65 U_MAIN.11@50.244,51.65 ; U_MAIN.11@49.976,51.65 50.057,51.65 50.15,51.65 U_MAIN.11@50.244,51.65 ; U_MAIN.11@50.376,51.65 U_MAIN.11 ; 51.45,51.65 51.369,51.65 51.275,51.65 51.181,51.65 51.088,51.65 50.994,51.65 50.9,51.65 50.806,51.65 U_MAIN.11 ; U_MAIN.50@63.35,51.55 64,51.55 63.9,51.65 63.994,51.65 U_MAIN.50 64.182,51.65 64.276,51.65 U_MAIN.50@64.369,51.65 ; U_MAIN.11@50.244,51.65 U_MAIN.11@50.338,51.65 ; U_MAIN.11@50.244,51.65 U_MAIN.11@50.337,51.65 ; U_MAIN.11@50.338,51.65 U_MAIN.11@50.432,51.65 ; U_MAIN.11@50.337,51.65 U_MAIN.11@50.431,51.65 ; U_MAIN.11@50.432,51.65 50.525,51.65 50.619,51.65 U_MAIN.11 ; U_MAIN.11@50.431,51.65 50.525,51.65 50.619,51.65 U_MAIN.11
  Top w0.28: U_SENSOR.8 98.579,52.15 98.759,52.15 98.926,52.234 ; U_SENSOR.8@98.59,52.158 98.681,52.15 98.775,52.15 98.8,52.15
  Top w0.296: U_MAIN.50@64.369,51.65 64.463,51.605 U_MAIN.50@64.825,51.616
  Top w0.3: U_SENSOR.8 U_SENSOR.8@98.5,52.182
  Top w0.325: v1(99.065,52.599) 99.092,52.319
  Top w0.347: U_SENSOR.8@98.5,52.182 U_SENSOR.8@98.59,52.158
  Top w0.35: U_LDO.5 37.717,58.41 37.984,58.557 38.251,58.704 38.4,58.138 38.925,57.262 39.625,57.262 39.975,57.438 39.975,59.013 39.539,59.513 39.6,59.5 39.625,59.45 39.975,59.8 40.197,60.171 40.416,60.39 40.41,60.662 ; 40.829,61.988 41.035,62.194 41.241,62.4 C_LDO_OUT.1 41.775,62.6 41.975,62.8 42.175,63 42.461,63 42.399,63.027 42.6,63.125 43.65,63.3 43.954,62.923 44.129,62.749 44.303,62.574 44.478,62.4 44.814,62.4 45.151,62.4 C_3V3_BULK.1 ; v1(47.819,50.816) 47.82,50.817 48.653,51.65 49.963,51.65 ; C_MCU_AVCC.1 49.963,51.65 ; J_DEBUG.1 48.97,65.882 C_3V3_BULK.1 ; 49.775,55.075 49.316,54.453 49.316,54.107 49.316,53.76 49.316,53.414 49.316,53.067 49.316,52.721 49.316,52.374 49.558,52.133 49.775,51.75 U_MAIN.11@50.376,51.65 ; 49.975,55.15 49.963,55.15 C_MCU_DVCC1.1 48.375,54.55 47.5,54.55 47.325,54.725 47.119,55.13 46.904,55.349 46.689,55.569 46.473,55.789 46.45,55.775 46.043,56.228 45.828,56.448 45.828,56.782 45.828,57.116 45.828,57.45 45.828,57.785 45.828,58.119 45.828,58.453 45.828,58.787 45.828,59.121 45.828,59.455 45.828,59.789 45.828,60.123 45.828,60.457 45.828,60.791 45.658,60.961 45.488,61.766 45.488,62.083 C_3V3_BULK.1 ; 51.45,51.65 51.463,51.65 61.03,51.641 61.6,50.65 62.2,50.65 63.1,51.55 63.35,51.55 ; v1(53.2,41.482) 53.2,41.69 R_MCU_RESET.2 ; 64.825,51.616 65.62,51.641 C_MCU_DVCC2.1 66.135,51.405 66.38,51.16 66.625,50.915 66.869,50.671 67.114,50.426 67.359,50.181 67.604,49.936 67.849,49.691 68.094,49.446 68.338,49.202 68.583,48.957 68.828,48.712 69.073,48.467 69.318,48.222 69.563,47.977 69.807,47.733 70.052,47.488 70.297,47.243 70.542,46.998 70.787,46.753 71.032,46.508 71.276,46.264 71.521,46.019 71.766,45.774 72.011,45.529 72.256,45.284 72.501,45.039 72.745,44.795 72.99,44.55 73.235,44.305 73.48,44.06 73.725,43.815 73.97,43.57 74.215,43.325 74.459,43.081 74.704,42.836 74.949,42.591 75.194,42.346 75.194,42.101 75.194,41.856 75.511,41.856 75.828,41.856 76.146,41.856 76.463,41.856 76.78,41.856 77.097,41.856 77.075,41.775 78.3,41.775 78.547,42.037 78.729,42.219 R_I2C_SDA.2 79.251,42.4 79.592,42.4 79.934,42.4 80.102,42.232 80.27,42.063 80.4,41.775 81.275,41.775 81.655,42.24 R_I2C_SCL.2 81.91,42.746 82.549,43.385 v1(82.684,43.52) ; v1(86,50.2) 86,52.707 89.657,56.365 89.854,56.364 C_SENSOR_VDD.1 91.89,58.4 C_SENSOR_VLOGIC.1 93.4,58.91 v1(93.4,59.2) ; U_SENSOR.13 97.731,49.319 97.942,49.319 v1(98.153,49.319) ; 98.8,52.15 98.869,52.15 98.962,52.15 99.056,52.15 99.091,52.15 99.133,52.192 99.192,52.192 v1(99.253,52.119) ; 98.926,52.234 99.092,52.319 ; 49.963,51.65 49.975,51.65 49.963,51.65
  Bottom w0.35: v1(47.819,50.816) 42.083,50.806 41.178,49.908 41.149,49.62 46.303,44.528 49.32,41.513 53.2,41.513 v1(53.2,41.482) ; v1(82.684,43.52) 82.684,46.831 85.998,50.146 85.998,50.198 v1(86,50.2) ; v1(93.4,59.2) 93.474,59.126 93.474,58.996 99.2,53.27 v1(99.253,52.119) ; v1(98.153,49.319) 98.19,49.282 98.314,49.282 98.526,49.494 98.738,49.706 98.95,49.917 98.964,50.253 98.979,50.588 98.993,50.923 99.007,51.258 99.022,51.593 99.036,51.928 99.051,52.263 v1(99.065,52.599)
XT2_IN: U_MAIN.69 Y_XT2.1 | length 3.5
  Top w0.12: U_MAIN.69 58.088,44.65 58.088,43.492 58.09,43.501 58.314,43.209 58.407,43.115 58.417,43.105 v1(58.417,42.871) ; v1(58.929,42.231) 58.975,42.185 59.018,42.185 59.303,41.9 Y_XT2.1
  Bottom w0.12: v1(58.417,42.871) 58.448,42.84 58.448,42.781 58.929,42.3 v1(58.929,42.231)
XT2_OUT: U_MAIN.70 Y_XT2.3 | length 3.5
  Top w0.15: Y_XT2.3 56.4,42.708 57.625,43.975 57.596,43.904 57.596,44.658 U_MAIN.70
pads on no net: J_USB.5 J_USB.11 J_USB.NPTH-1 J_USB.NPTH-2 U_LDO.4 U_MAIN.1 U_MAIN.2 U_MAIN.3 U_MAIN.4 U_MAIN.5 U_MAIN.6 U_MAIN.7 U_MAIN.8 U_MAIN.9 U_MAIN.10 U_MAIN.12 U_MAIN.13 U_MAIN.15 U_MAIN.16 U_MAIN.17 U_MAIN.21 U_MAIN.22 U_MAIN.23 U_MAIN.25 U_MAIN.26 U_MAIN.27 U_MAIN.28 U_MAIN.29 U_MAIN.30 U_MAIN.31 U_MAIN.32 U_MAIN.33 U_MAIN.34 U_MAIN.35 U_MAIN.36 U_MAIN.39 U_MAIN.42 U_MAIN.43 U_MAIN.44 U_MAIN.45 U_MAIN.46 U_MAIN.47 U_MAIN.48 U_MAIN.51 U_MAIN.52 U_MAIN.53 U_MAIN.54 U_MAIN.55 U_MAIN.56 U_MAIN.57 U_MAIN.58 U_MAIN.59 U_MAIN.60 U_MAIN.72 U_MAIN.73 U_MAIN.74 U_MAIN.75 U_MAIN.77 U_MAIN.78 U_MAIN.79 U_MAIN.80 U_SENSOR.2 U_SENSOR.3 U_SENSOR.4 U_SENSOR.5 U_SENSOR.6 U_SENSOR.7 U_SENSOR.14 U_SENSOR.15 U_SENSOR.16 U_SENSOR.17 U_SENSOR.19 U_SENSOR.21 U_SENSOR.22

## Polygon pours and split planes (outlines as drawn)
GND on Bottom (solid): 107.1,77.1 25.7,77.1 25.7,25.7 107.1,25.7
GND on Bottom (solid): 60.181,47.478 60.274,47.338 60.273,47.385 60.273,47.394 60.196,47.472 60.191,47.477
GND on Bottom (solid): 35.387,49.46 35.391,49.448 35.394,49.46
GND on Bottom (solid): 33.595,49.354 33.595,49.254 33.665,49.185 33.655,49.217 33.646,49.305 33.649,49.331 33.623,49.339
GND on Bottom (solid): 35.237,48.967 35.193,48.931 35.115,48.889 35.031,48.864 34.943,48.855 34.096,48.855 34.008,48.864 33.977,48.874 34.909,47.942

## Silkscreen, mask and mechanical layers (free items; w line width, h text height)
Top Overlay:
  text "2L • BOTTOM GND POUR" at 47.4,75.4 h0.48
  text "I2C 0x68 • USB-C" at 85.4,75.4 h0.55
  text "MPU-6050" at 88.4,28.9 h0.58
  text "QUICK CONFIGURE • SENSOR" at 66.4,27.4 h0.72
